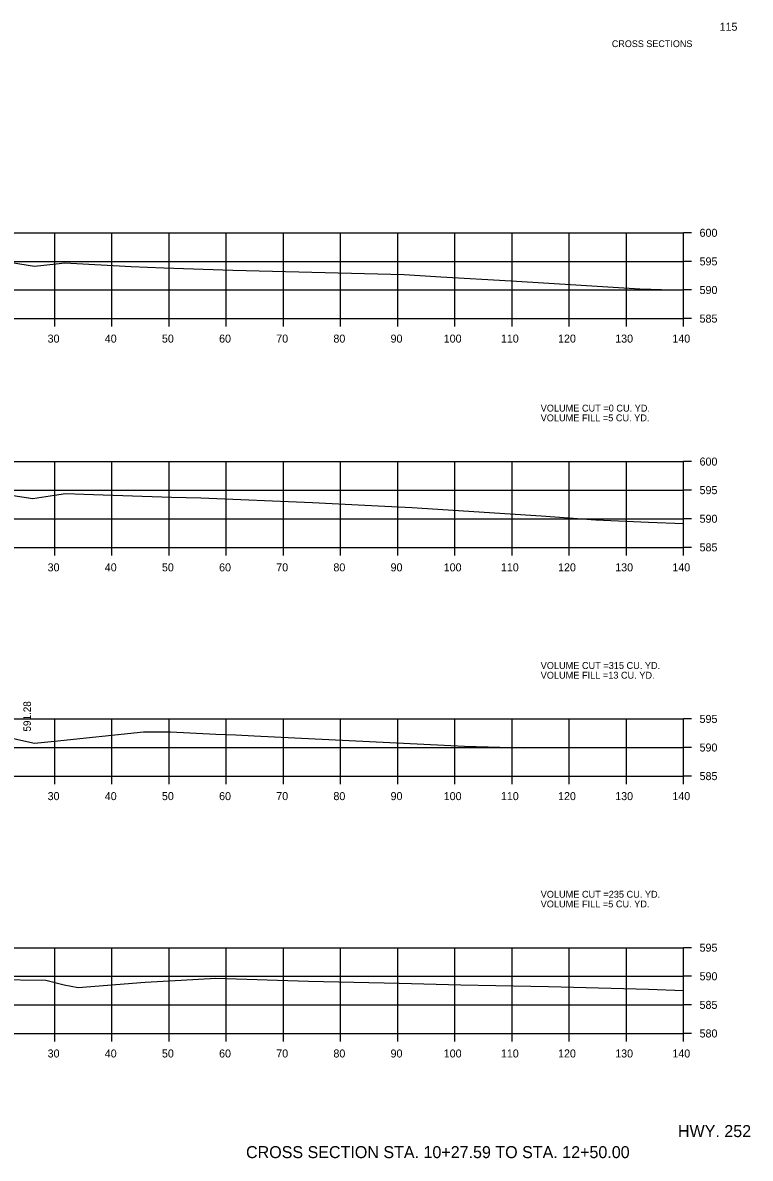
# Model space of a CAD drawing. Extents: x 642114 to 642416, y 286928 to 293347.
# Drawn here: x 642284.6 to 642411.9, y 293148.8 to 293347.3 of the extents above; entities that cross this region are included whole.
import ezdxf

# ---------------------------------------------------------------- set-up
doc = ezdxf.new("R2010")
doc.units = 0
for name, color, linetype in [('R_Axis', 7, 'Continuous'), ('R_Axis Annot', 7, 'Continuous'), ('R_Border', 7, 'Continuous'), ('R_Border Notes', 7, 'Continuous'), ('R_Draft', 7, 'Continuous'), ('R_Exist Surface', 7, 'Continuous'), ('R_Grid', 7, 'Continuous'), ('R_Xsect Elev', 7, 'Continuous')]:
    doc.layers.add(name, color=color, linetype=linetype)

msp = doc.modelspace()

# ---------------------------------------------------------------- linework, layer by layer
at = {"layer": 'R_Axis'}
for p, q in [((642400.24, 293295.61), (642400.24, 293310.61)), ((642401.64, 293310.61), (642400.24, 293310.61)), ((642401.64, 293305.61), (642400.24, 293305.61)), ((642401.64, 293300.61), (642400.24, 293300.61)), ((642120.24, 293295.61), (642400.24, 293295.61)), ((642290.24, 293294.21), (642290.24, 293295.61)), ((642300.24, 293294.21), (642300.24, 293295.61)), ((642310.24, 293294.21), (642310.24, 293295.61)), ((642320.24, 293294.21), (642320.24, 293295.61)), ((642330.24, 293294.21), (642330.24, 293295.61)), ((642340.24, 293294.21), (642340.24, 293295.61)), ((642350.24, 293294.21), (642350.24, 293295.61)), ((642360.24, 293294.21), (642360.24, 293295.61)), ((642370.24, 293294.21), (642370.24, 293295.61)), ((642380.24, 293294.21), (642380.24, 293295.61)), ((642390.24, 293294.21), (642390.24, 293295.61)), ((642400.24, 293294.21), (642400.24, 293295.61)), ((642401.64, 293295.61), (642400.24, 293295.61)), ((642400.24, 293255.61), (642400.24, 293270.61)), ((642401.64, 293270.61), (642400.24, 293270.61)), ((642401.64, 293265.61), (642400.24, 293265.61)), ((642401.64, 293260.61), (642400.24, 293260.61)), ((642120.24, 293255.61), (642400.24, 293255.61)), ((642290.24, 293254.21), (642290.24, 293255.61)), ((642300.24, 293254.21), (642300.24, 293255.61)), ((642310.24, 293254.21), (642310.24, 293255.61)), ((642320.24, 293254.21), (642320.24, 293255.61)), ((642330.24, 293254.21), (642330.24, 293255.61)), ((642340.24, 293254.21), (642340.24, 293255.61)), ((642350.24, 293254.21), (642350.24, 293255.61)), ((642360.24, 293254.21), (642360.24, 293255.61)), ((642370.24, 293254.21), (642370.24, 293255.61)), ((642380.24, 293254.21), (642380.24, 293255.61)), ((642390.24, 293254.21), (642390.24, 293255.61)), ((642400.24, 293254.21), (642400.24, 293255.61)), ((642401.64, 293255.61), (642400.24, 293255.61)), ((642400.24, 293215.61), (642400.24, 293225.61)), ((642401.64, 293225.61), (642400.24, 293225.61)), ((642401.64, 293220.61), (642400.24, 293220.61)), ((642120.24, 293215.61), (642400.24, 293215.61)), ((642290.24, 293214.21), (642290.24, 293215.61)), ((642300.24, 293214.21), (642300.24, 293215.61)), ((642310.24, 293214.21), (642310.24, 293215.61)), ((642320.24, 293214.21), (642320.24, 293215.61)), ((642330.24, 293214.21), (642330.24, 293215.61)), ((642340.24, 293214.21), (642340.24, 293215.61)), ((642350.24, 293214.21), (642350.24, 293215.61)), ((642360.24, 293214.21), (642360.24, 293215.61)), ((642370.24, 293214.21), (642370.24, 293215.61)), ((642380.24, 293214.21), (642380.24, 293215.61)), ((642390.24, 293214.21), (642390.24, 293215.61)), ((642400.24, 293214.21), (642400.24, 293215.61)), ((642401.64, 293215.61), (642400.24, 293215.61)), ((642400.24, 293170.61), (642400.24, 293185.61)), ((642401.64, 293185.61), (642400.24, 293185.61)), ((642401.64, 293180.61), (642400.24, 293180.61)), ((642401.64, 293175.61), (642400.24, 293175.61)), ((642120.24, 293170.61), (642400.24, 293170.61)), ((642290.24, 293169.21), (642290.24, 293170.61)), ((642300.24, 293169.21), (642300.24, 293170.61)), ((642310.24, 293169.21), (642310.24, 293170.61)), ((642320.24, 293169.21), (642320.24, 293170.61)), ((642330.24, 293169.21), (642330.24, 293170.61)), ((642340.24, 293169.21), (642340.24, 293170.61)), ((642350.24, 293169.21), (642350.24, 293170.61)), ((642360.24, 293169.21), (642360.24, 293170.61)), ((642370.24, 293169.21), (642370.24, 293170.61)), ((642380.24, 293169.21), (642380.24, 293170.61)), ((642390.24, 293169.21), (642390.24, 293170.61)), ((642400.24, 293169.21), (642400.24, 293170.61)), ((642401.64, 293170.61), (642400.24, 293170.61))]:
    msp.add_line(p, q, dxfattribs=at)
at = {"layer": 'R_Exist Surface'}
for points in [[(642280.02, 293305.85), (642286.69, 293304.77), (642290.48, 293305.18), (642292.01, 293305.33), (642303.59, 293304.73), (642309.31, 293304.46), (642321.37, 293304.06), (642351.38, 293303.34), (642357.78, 293302.92), (642370.06, 293302.19), (642382.31, 293301.43), (642392.61, 293300.84), (642400.24, 293300.58)], [(642278.35, 293265.36), (642286.37, 293264.13), (642290.18, 293264.72), (642292.12, 293265.01), (642295.31, 293264.92), (642310.64, 293264.41), (642315.77, 293264.26), (642335.33, 293263.43), (642344.49, 293262.98), (642352.69, 293262.58), (642375.3, 293261.14), (642384.91, 293260.44), (642394.11, 293260.02), (642400.24, 293259.78)], [(642278.8, 293223.1), (642285.84, 293221.56), (642286.67, 293221.39), (642290.16, 293221.71), (642305.74, 293223.34), (642310.47, 293223.33), (642318.39, 293222.97), (642321.89, 293222.82), (642325.13, 293222.67), (642361.94, 293220.86), (642372.21, 293220.54)], [(642270.74, 293180.19), (642288.64, 293179.92), (642291.85, 293179.14), (642294.34, 293178.63), (642306.04, 293179.56), (642312.34, 293179.93), (642318.42, 293180.28), (642334.62, 293179.78), (642350.47, 293179.41), (642361.28, 293179.11), (642373.54, 293178.87), (642376.61, 293178.8), (642387.57, 293178.51), (642394.12, 293178.35), (642400.24, 293178.14)]]:
    msp.add_lwpolyline(points, dxfattribs=at)
at = {"layer": 'R_Grid'}
for p, q in [((642120.24, 293310.61), (642400.24, 293310.61)), ((642290.24, 293295.61), (642290.24, 293310.61)), ((642300.24, 293295.61), (642300.24, 293310.61)), ((642310.24, 293295.61), (642310.24, 293310.61)), ((642320.24, 293295.61), (642320.24, 293310.61)), ((642330.24, 293295.61), (642330.24, 293310.61)), ((642340.24, 293295.61), (642340.24, 293310.61)), ((642350.24, 293295.61), (642350.24, 293310.61)), ((642360.24, 293295.61), (642360.24, 293310.61)), ((642370.24, 293295.61), (642370.24, 293310.61)), ((642380.24, 293295.61), (642380.24, 293310.61)), ((642390.24, 293295.61), (642390.24, 293310.61)), ((642400.24, 293295.61), (642400.24, 293310.61)), ((642120.24, 293305.61), (642400.24, 293305.61)), ((642120.24, 293300.61), (642400.24, 293300.61)), ((642120.24, 293295.61), (642400.24, 293295.61)), ((642120.24, 293270.61), (642400.24, 293270.61)), ((642290.24, 293255.61), (642290.24, 293270.61)), ((642300.24, 293255.61), (642300.24, 293270.61)), ((642310.24, 293255.61), (642310.24, 293270.61)), ((642320.24, 293255.61), (642320.24, 293270.61)), ((642330.24, 293255.61), (642330.24, 293270.61)), ((642340.24, 293255.61), (642340.24, 293270.61)), ((642350.24, 293255.61), (642350.24, 293270.61)), ((642360.24, 293255.61), (642360.24, 293270.61)), ((642370.24, 293255.61), (642370.24, 293270.61)), ((642380.24, 293255.61), (642380.24, 293270.61)), ((642390.24, 293255.61), (642390.24, 293270.61)), ((642400.24, 293255.61), (642400.24, 293270.61)), ((642120.24, 293265.61), (642400.24, 293265.61)), ((642120.24, 293260.61), (642400.24, 293260.61)), ((642120.24, 293255.61), (642400.24, 293255.61)), ((642120.24, 293225.61), (642400.24, 293225.61)), ((642290.24, 293215.61), (642290.24, 293225.61)), ((642300.24, 293215.61), (642300.24, 293225.61)), ((642310.24, 293215.61), (642310.24, 293225.61)), ((642320.24, 293215.61), (642320.24, 293225.61)), ((642330.24, 293215.61), (642330.24, 293225.61)), ((642340.24, 293215.61), (642340.24, 293225.61)), ((642350.24, 293215.61), (642350.24, 293225.61)), ((642360.24, 293215.61), (642360.24, 293225.61)), ((642370.24, 293215.61), (642370.24, 293225.61)), ((642380.24, 293215.61), (642380.24, 293225.61)), ((642390.24, 293215.61), (642390.24, 293225.61)), ((642400.24, 293215.61), (642400.24, 293225.61)), ((642120.24, 293220.61), (642400.24, 293220.61)), ((642120.24, 293215.61), (642400.24, 293215.61)), ((642120.24, 293185.61), (642400.24, 293185.61)), ((642290.24, 293170.61), (642290.24, 293185.61)), ((642300.24, 293170.61), (642300.24, 293185.61)), ((642310.24, 293170.61), (642310.24, 293185.61)), ((642320.24, 293170.61), (642320.24, 293185.61)), ((642330.24, 293170.61), (642330.24, 293185.61)), ((642340.24, 293170.61), (642340.24, 293185.61)), ((642350.24, 293170.61), (642350.24, 293185.61)), ((642360.24, 293170.61), (642360.24, 293185.61)), ((642370.24, 293170.61), (642370.24, 293185.61)), ((642380.24, 293170.61), (642380.24, 293185.61)), ((642390.24, 293170.61), (642390.24, 293185.61)), ((642400.24, 293170.61), (642400.24, 293185.61)), ((642120.24, 293180.61), (642400.24, 293180.61)), ((642120.24, 293175.61), (642400.24, 293175.61)), ((642120.24, 293170.61), (642400.24, 293170.61))]:
    msp.add_line(p, q, dxfattribs=at)

# ---------------------------------------------------------------- texts
at = {"layer": 'R_Axis Annot'}
for s, height, p in [('600', 1.4, (642403.04, 293309.91)), ('595', 1.4, (642403.04, 293304.91)), ('590', 1.4, (642403.04, 293299.91)), ('585', 1.4, (642403.04, 293294.91)), ('30', 1.4, (642288.98, 293291.41)), ('40', 1.4, (642298.98, 293291.41)), ('50', 1.4, (642308.98, 293291.41)), ('60', 1.4, (642318.98, 293291.41)), ('70', 1.4, (642328.98, 293291.41)), ('80', 1.4, (642338.98, 293291.41)), ('90', 1.4, (642348.98, 293291.41)), ('100', 1.4, (642358.28, 293291.41)), ('110', 1.4, (642368.28, 293291.41)), ('120', 1.4, (642378.28, 293291.41)), ('130', 1.4, (642388.28, 293291.41)), ('140', 1.4, (642398.28, 293291.41)), ('600', 1.4, (642403.04, 293269.91)), ('595', 1.4, (642403.04, 293264.91)), ('590', 1.4, (642403.04, 293259.91)), ('585', 1.4, (642403.04, 293254.91)), ('30', 1.4, (642288.98, 293251.41)), ('40', 1.4, (642298.98, 293251.41)), ('50', 1.4, (642308.98, 293251.41)), ('60', 1.4, (642318.98, 293251.41)), ('70', 1.4, (642328.98, 293251.41)), ('80', 1.4, (642338.98, 293251.41)), ('90', 1.4, (642348.98, 293251.41)), ('100', 1.4, (642358.28, 293251.41)), ('110', 1.4, (642368.28, 293251.41)), ('120', 1.4, (642378.28, 293251.41)), ('130', 1.4, (642388.28, 293251.41)), ('140', 1.4, (642398.28, 293251.41)), ('595', 1.4, (642403.04, 293224.91)), ('590', 1.4, (642403.04, 293219.91)), ('585', 1.4, (642403.04, 293214.91)), ('30', 1.4, (642288.98, 293211.41)), ('40', 1.4, (642298.98, 293211.41)), ('50', 1.4, (642308.98, 293211.41)), ('60', 1.4, (642318.98, 293211.41)), ('70', 1.4, (642328.98, 293211.41)), ('80', 1.4, (642338.98, 293211.41)), ('90', 1.4, (642348.98, 293211.41)), ('100', 1.4, (642358.28, 293211.41)), ('110', 1.4, (642368.28, 293211.41)), ('120', 1.4, (642378.28, 293211.41)), ('130', 1.4, (642388.28, 293211.41)), ('140', 1.4, (642398.28, 293211.41)), ('595', 1.4, (642403.04, 293184.91)), ('590', 1.4, (642403.04, 293179.91)), ('585', 1.4, (642403.04, 293174.91)), ('580', 1.4, (642403.04, 293169.91)), ('30', 1.4, (642288.98, 293166.41)), ('40', 1.4, (642298.98, 293166.41)), ('50', 1.4, (642308.98, 293166.41)), ('60', 1.4, (642318.98, 293166.41)), ('70', 1.4, (642328.98, 293166.41)), ('80', 1.4, (642338.98, 293166.41)), ('90', 1.4, (642348.98, 293166.41)), ('100', 1.4, (642358.28, 293166.41)), ('110', 1.4, (642368.28, 293166.41)), ('120', 1.4, (642378.28, 293166.41)), ('130', 1.4, (642388.28, 293166.41)), ('140', 1.4, (642398.28, 293166.41)), ('HWY. 252', 2.1, (642399.26, 293152.49)), ('CROSS SECTION STA. 10+27.59 TO STA. 12+50.00', 2.1, (642323.69, 293148.81))]:
    msp.add_text(s, height=height, dxfattribs=at).set_placement(p)
at = {"layer": 'R_Border'}
msp.add_text('115', height=1.4, dxfattribs=at).set_placement((642406.54, 293345.94))
at = {"layer": 'R_Border Notes'}
msp.add_text('    CROSS SECTIONS    ', height=1.178, dxfattribs=at).set_placement((642385.94, 293343.08))
at = {"layer": 'R_Draft'}
for s, p in [('VOLUME CUT =0 CU. YD.', (642375.24, 293279.35)), ('VOLUME FILL =5 CU. YD.', (642375.24, 293277.65)), ('VOLUME CUT =315 CU. YD.', (642375.24, 293234.35)), ('VOLUME FILL =13 CU. YD.', (642375.24, 293232.65)), ('VOLUME CUT =235 CU. YD.', (642375.24, 293194.35)), ('VOLUME FILL =5 CU. YD.', (642375.24, 293192.65))]:
    msp.add_text(s, height=1.2, dxfattribs=at).set_placement(p)
at = {"layer": 'R_Xsect Elev'}
msp.add_text(' 591.28', height=1.3, rotation=90, dxfattribs=at).set_placement((642286.05, 293222.91))

doc.saveas('drawing.dxf')
